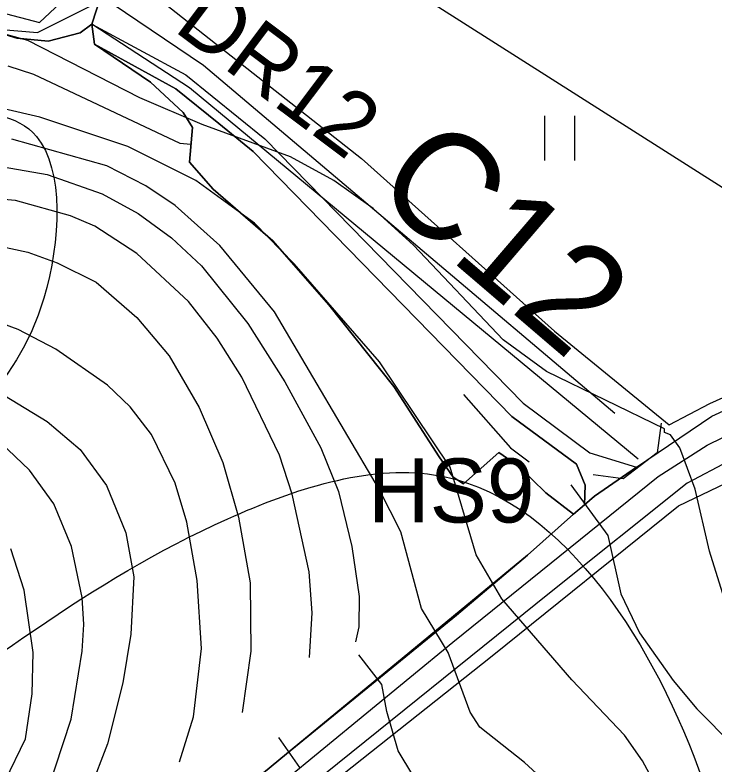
# Model space of a CAD drawing. Extents: x -684583 to -680383, y -1157874 to -1154904.
# Drawn here: x -683367.4 to -683203.8, y -1157172.5 to -1156997 of the extents above; entities that cross this region are included whole.
import ezdxf

# ---------------------------------------------------------------- set-up
doc = ezdxf.new("R2010")
doc.units = 0
for name, color, linetype in [('01_DOPRAVA', 7, 'Continuous'), ('01_PRVKY PRŮZKUMU', 7, 'Continuous'), ('01_VRSTEVNICE', 7, 'Continuous'), ('02_KULTURY STAV', 7, 'Continuous'), ('03_PC_OBJEKTY_NÁVRH', 7, 'Continuous'), ('03_PC_OBJEKTY_STAV', 7, 'Continuous'), ('03_PC_POPIS_STAV', 7, 'Continuous'), ('03_PC_STAV', 7, 'Continuous'), ('04_ZPF_OP_ORGAN', 7, 'Continuous'), ('05_VHO_V_TOK', 7, 'Continuous'), ('06_BIOGEOGRAFIE', 7, 'Continuous'), ('06_ÚSES_BK', 7, 'Continuous')]:
    doc.layers.add(name, color=color, linetype=linetype)

msp = doc.modelspace()

# ---------------------------------------------------------------- linework, layer by layer
at = {"layer": '01_DOPRAVA'}
msp.add_lwpolyline([(-683848.9, -1157421.35), (-683768.73, -1157372.16), (-683751.13, -1157356.37), (-683692.43, -1157298.55), (-683668.13, -1157274.02), (-683656.09, -1157268.45), (-683636.34, -1157266.75), (-683560.15, -1157260.5), (-683520.41, -1157256.3), (-683504.28, -1157253.8), (-683468.06, -1157246.75), (-683377.9, -1157224.15), (-683360.31, -1157216.54), (-683346.34, -1157208.36), (-683325.33, -1157193.59), (-683264.93, -1157143.95), (-683216.9, -1157105.1), (-683205.43, -1157097.83), (-683190.89, -1157090.67), (-683176.02, -1157086.02), (-683159.33, -1157083.06), (-683139, -1157080.79)], dxfattribs=at)
at = {"layer": '01_PRVKY PRŮZKUMU'}
msp.add_lwpolyline([(-683389.86, -1156998.77), (-683362.19, -1157001.09), (-683347.07, -1156993.53), (-683333.41, -1156993.53), (-683286.36, -1157030.61), (-683241.13, -1157071.1), (-683214.31, -1157093.06), (-683204.8, -1157088.06), (-683190.17, -1157081.47)], dxfattribs=at)
at = {"layer": '01_VRSTEVNICE'}
for points in [[(-683173.18, -1157170.81), (-683173.59, -1157160.59), (-683179.58, -1157153.03), (-683188.14, -1157148.33), (-683193.28, -1157144.47), (-683197.7, -1157139.48), (-683201.41, -1157133.63), (-683204.83, -1157122.65), (-683208.25, -1157108.1), (-683211.82, -1157098.4), (-683213.96, -1157095.4), (-683215.39, -1157094.83), (-683215.39, -1157093.98), (-683243.06, -1157080.57), (-683253.19, -1157073.15), (-683274.16, -1157050.9), (-683283.57, -1157042.34), (-683292.84, -1157035.78), (-683302.97, -1157030.22), (-683323.65, -1157022.66), (-683338.2, -1157016.38), (-683364.45, -1157002.97), (-683378.14, -1156999.26)], [(-683326.36, -1157027.36), (-683328.79, -1157027.08), (-683363.02, -1157010.96), (-683369.01, -1157008.96)], [(-683184.43, -1157261.16), (-683198.13, -1157243.61), (-683206.97, -1157226.49), (-683213.25, -1157219.79), (-683215.39, -1157215.37), (-683216.81, -1157209.66), (-683217.1, -1157204.24), (-683215.53, -1157188.27), (-683216.24, -1157182.56), (-683217.81, -1157176.85), (-683220.52, -1157171.72), (-683224.8, -1157165.73), (-683237.07, -1157152.75), (-683253.47, -1157133.78), (-683259.46, -1157123.51), (-683265.6, -1157102.96), (-683282.14, -1157078.29), (-683302.11, -1157055.32), (-683311.39, -1157045.76), (-683325.08, -1157035.78), (-683341.06, -1157027.79), (-683361.6, -1157020.95), (-683377.57, -1157017.24)], [(-683236.93, -1157182.42), (-683248.19, -1157172.15), (-683258.61, -1157163.87), (-683260.89, -1157160.31), (-683266.03, -1157146.33), (-683272.3, -1157136.06), (-683277.15, -1157118.09), (-683282.14, -1157108.24), (-683306.68, -1157066.59), (-683319.52, -1157051.04), (-683329.93, -1157041.63), (-683336.78, -1157037.06), (-683345.91, -1157032.36), (-683368.16, -1157026.08)], [(-683373.86, -1157031.93), (-683359.88, -1157034.35), (-683347.05, -1157038.92), (-683338.63, -1157043.48), (-683330.79, -1157049.19), (-683323.8, -1157055.75), (-683312.95, -1157069.3), (-683304.25, -1157082.99), (-683295.84, -1157098.4), (-683291.7, -1157108.67), (-683288.56, -1157121.51), (-683286.85, -1157133.21), (-683286.99, -1157140.34), (-683287.71, -1157143.9)], [(-683298.47, -1157147.56), (-683297.85, -1157137.06), (-683298.55, -1157127.5), (-683302.54, -1157109.24), (-683305.54, -1157100.11), (-683314.38, -1157081.85), (-683320.09, -1157072.72), (-683326.79, -1157064.17), (-683338.92, -1157052.9), (-683348.76, -1157046.48), (-683354.46, -1157044.05), (-683367.3, -1157040.49), (-683380.14, -1157039.35)], [(-683373.58, -1157050.61), (-683364.45, -1157052.61), (-683357.6, -1157055.04), (-683348.47, -1157059.6), (-683338.92, -1157067.88), (-683331.36, -1157076.86), (-683324.37, -1157088.99), (-683318.8, -1157101.82), (-683315.09, -1157114.66), (-683312.38, -1157130.07), (-683312.24, -1157146.04), (-683314.24, -1157160.45)], [(-683328.9, -1157171.99), (-683325.65, -1157161.45), (-683323.8, -1157145.47), (-683324.79, -1157129.5), (-683327.22, -1157115.8), (-683329.93, -1157106.67), (-683335.49, -1157095.26), (-683340.48, -1157088.84), (-683345.76, -1157083.71), (-683357.89, -1157075.29), (-683366.73, -1157070.73), (-683376.72, -1157067.02)], [(-683373.58, -1157083.99), (-683359.88, -1157092.27), (-683352.18, -1157098.83), (-683346.05, -1157107.24), (-683341.48, -1157118.37), (-683339.63, -1157128.64), (-683340.34, -1157142.05), (-683342.2, -1157153.46), (-683345.76, -1157167.73), (-683349.9, -1157178.57), (-683351.33, -1157186.27), (-683351.33, -1157193.97), (-683349.9, -1157199.68), (-683344.76, -1157208.09)], [(-683262.42, -1157085.93), (-683251.47, -1157098.4), (-683247.05, -1157101.68)], [(-683371.01, -1157210.66), (-683365.45, -1157195.97), (-683354.32, -1157162.02), (-683351.75, -1157146.04), (-683351.33, -1157139.77), (-683351.75, -1157133.49), (-683354.18, -1157121.51), (-683358.32, -1157111.52), (-683364.02, -1157103.68), (-683370.73, -1157097.26)], [(-683237.35, -1157107.1), (-683228.65, -1157118.94), (-683225.66, -1157132.63), (-683221.23, -1157141.76), (-683213.39, -1157152.89), (-683207.83, -1157159.59), (-683190.71, -1157176.85), (-683186.29, -1157183.7), (-683183.01, -1157192.83), (-683180.15, -1157211.09), (-683174.45, -1157232.63)], [(-683369.73, -1157176.43), (-683365.02, -1157166.58), (-683363.45, -1157156.03), (-683363.17, -1157146.33), (-683365.3, -1157131.78), (-683368.44, -1157122.08)], [(-683157.9, -1157343.18), (-683171.45, -1157318.64), (-683184.58, -1157292.97), (-683188.14, -1157287.26), (-683192.85, -1157281.7), (-683198.7, -1157276.13), (-683209.54, -1157268.86), (-683222.23, -1157257.73), (-683229.65, -1157248.75), (-683237.21, -1157237.34), (-683242.35, -1157225.92), (-683246.62, -1157208.81), (-683251.47, -1157197.4), (-683257.04, -1157188.84), (-683260.32, -1157185.56), (-683274.3, -1157175.14), (-683277.72, -1157169.44), (-683280.43, -1157160.17), (-683281.57, -1157153.89), (-683286.99, -1157146.9)], [(-683300.73, -1157173.29), (-683305.67, -1157166.29)]]:
    msp.add_lwpolyline(points, dxfattribs=at)
at = {"layer": '02_KULTURY STAV'}
for points in [[(-683370.86, -1157001.24), (-683367.03, -1157002.46), (-683359.7, -1157003.17), (-683352.15, -1157001.15), (-683349.45, -1156999.14), (-683343.69, -1156981.37), (-683341.48, -1156976.18), (-683337.83, -1156966.11), (-683344.97, -1156965.28), (-683350.67, -1156972.37), (-683355.24, -1156986.1), (-683364.12, -1156994.87), (-683372.87, -1156988.03)], [(-683203.65, -1156985.03), (-683213.41, -1156987.19), (-683225.95, -1156987.87), (-683230.28, -1156988.44), (-683246.03, -1156994.49), (-683251.36, -1156993.14), (-683266.62, -1156985.44), (-683277.18, -1156975.14), (-683289.55, -1156972.59), (-683301.39, -1156969.2), (-683319.75, -1156985.6), (-683331.68, -1156983.88), (-683341.48, -1156976.18), (-683343.69, -1156981.37), (-683349.45, -1156999.14), (-683327.49, -1157011.01), (-683308.96, -1157026.01), (-683248.52, -1157087.99), (-683232.88, -1157099.6), (-683221.99, -1157102.98), (-683204.36, -1157091.01), (-683192.73, -1157085.68)], [(-683370.86, -1157001.24), (-683367.03, -1157002.46), (-683359.7, -1157003.17), (-683352.15, -1157001.15), (-683349.45, -1156999.14), (-683348.81, -1157003.81), (-683335.7, -1157012.73), (-683328.09, -1157019.82), (-683325.91, -1157023.37), (-683326.6, -1157031.51), (-683321.09, -1157037.79), (-683307.07, -1157049.92), (-683293.99, -1157064.88), (-683278.77, -1157084.06), (-683268.17, -1157100.5), (-683264.9, -1157105.28), (-683262.45, -1157106.87), (-683254.22, -1157099.55), (-683249.56, -1157102.68), (-683243.17, -1157108.95), (-683236.68, -1157113.93), (-683247.5, -1157123.53), (-683303.88, -1157170.13), (-683333.9, -1157194.91)], [(-683243.5, -1157020.6), (-683243.5, -1157031.1)], [(-683236.5, -1157020.6), (-683236.5, -1157031.1)], [(-683333.9, -1157194.91), (-683303.88, -1157170.13), (-683264.09, -1157137.63), (-683247.5, -1157123.53), (-683236.68, -1157113.93), (-683234.11, -1157111.74), (-683231.81, -1157109.78), (-683221.99, -1157102.98), (-683204.36, -1157091.01), (-683192.73, -1157085.68), (-683177.22, -1157080.76), (-683161.41, -1157076.94), (-683151.59, -1157072.03), (-683141.73, -1157064.85), (-683156.58, -1157097.8), (-683159.7, -1157092.45), (-683164.59, -1157091.26), (-683175.94, -1157092.6), (-683190.37, -1157096.97), (-683200.33, -1157101.53), (-683210.06, -1157106.68), (-683242.35, -1157132.43), (-683297.96, -1157177.33)]]:
    msp.add_lwpolyline(points, dxfattribs=at)
for points in [[(-683349.45, -1156999.14), (-683327.49, -1157011.01), (-683308.96, -1157026.01), (-683248.52, -1157087.99), (-683232.88, -1157099.6), (-683221.99, -1157102.98), (-683231.81, -1157109.78), (-683234.11, -1157111.74), (-683233.99, -1157107.14), (-683236, -1157102.26), (-683251.17, -1157091.07), (-683311.69, -1157028.98), (-683319.75, -1157022.45), (-683329.81, -1157014.3), (-683348.81, -1157003.81)], [(-683348.81, -1157003.81), (-683329.81, -1157014.3), (-683319.75, -1157022.45), (-683311.69, -1157028.98), (-683251.17, -1157091.07), (-683236, -1157102.26), (-683233.99, -1157107.14), (-683234.11, -1157111.74), (-683236.68, -1157113.93), (-683243.17, -1157108.95), (-683249.56, -1157102.68), (-683254.22, -1157099.55), (-683262.45, -1157106.87), (-683264.9, -1157105.28), (-683268.17, -1157100.5), (-683278.77, -1157084.06), (-683293.99, -1157064.88), (-683307.07, -1157049.92), (-683321.09, -1157037.79), (-683326.6, -1157031.51), (-683325.91, -1157023.37), (-683328.09, -1157019.82), (-683335.7, -1157012.73)]]:
    msp.add_lwpolyline(points, close=True, dxfattribs=at)
at = {"layer": '03_PC_OBJEKTY_NÁVRH'}
msp.add_lwpolyline([(-683226.99, -1157090.37), (-683323.32, -1157008.82), (-683344.73, -1156994.4)], dxfattribs=at)
at = {"layer": '03_PC_OBJEKTY_STAV'}
msp.add_lwpolyline([(-683216.16, -1157092.62), (-683217.11, -1157099.62), (-683225.07, -1157105.68), (-683232.08, -1157104.73)], dxfattribs=at)
at = {"layer": '03_PC_STAV'}
msp.add_lwpolyline([(-683221.6, -1157101.06), (-683326.6, -1157014.04), (-683349.45, -1156999.14)], dxfattribs=at)
at = {"layer": '04_ZPF_OP_ORGAN'}
msp.add_lwpolyline([(-683343.12, -1157216.48), (-683255.77, -1157147.12), (-683212.14, -1157111.99), (-683188, -1157100.46), (-683171.81, -1157095.24), (-683160.28, -1157100.46), (-683176.2, -1157149.05), (-683182.23, -1157222.89), (-683169.61, -1157275.32), (-683083.46, -1157449.64), (-683050.81, -1157531.17), (-683043.68, -1157605.57), (-683055.75, -1157649.76), (-683061.24, -1157640.16), (-683077.15, -1157575.37), (-683110.35, -1157581.68), (-683135.87, -1157597.03), (-683152.6, -1157616.55), (-683323.54, -1157289.05), (-683339.45, -1157238.26)], close=True, dxfattribs=at)
at = {"layer": '05_VHO_V_TOK'}
msp.add_lwpolyline([(-683378.73, -1156994.28), (-683361.67, -1156998.74), (-683352.07, -1156989.61), (-683342.95, -1156971), (-683334.18, -1156973.73), (-683324.11, -1156981.32), (-683316.17, -1156975.87), (-683302.3, -1156964.48), (-683279.9, -1156970.88), (-683268.64, -1156977.76), (-683256.2, -1156986.41), (-683238.07, -1156986.41), (-683206.55, -1156982.5), (-683191.86, -1156974.2), (-683180.36, -1156978.71), (-683174.44, -1156992.7), (-683172.9, -1157010.12), (-683165.9, -1157018.9), (-683149.43, -1157022.45), (-683104.87, -1157050.79), (-683100.25, -1157059.8), (-683098, -1157072.96), (-683095.63, -1157123.11), (-683121.58, -1157197.8)], dxfattribs=at)
at = {"layer": '06_BIOGEOGRAFIE'}
for points in [[(-683605.53, -1156693.94), (-683552.15, -1156773.17), (-683505.66, -1156862.74), (-683385.12, -1156876.52), (-683240.48, -1156867.91), (-682983.91, -1156935.09), (-682923.69, -1156998.38), (-682921.97, -1157094.84), (-682923.69, -1157198.19), (-682892.7, -1157272.26), (-682746.33, -1157329.1), (-682572.41, -1157337.72), (-682417.44, -1157289.49), (-682386.73, -1157266.62)], [(-683662.04, -1156787.77), (-683658.6, -1156877.34), (-683631.05, -1156927.29), (-683541.5, -1156975.52), (-683489.85, -1157028.92), (-683414.08, -1157027.2), (-683362.42, -1157025.48), (-683360.7, -1157063.37), (-683464.02, -1157132.27), (-683493.29, -1157163.28), (-683474.35, -1157189.11), (-683407.19, -1157171.89), (-683317.65, -1157115.05), (-683269.44, -1157104.71), (-683207.44, -1157173.61), (-683186.78, -1157259.74), (-683105.85, -1157416.48), (-683069.69, -1157530.17), (-683073.13, -1157580.12), (-683097.24, -1157628.35), (-683264.27, -1157657.63), (-683431.3, -1157647.3), (-683531.17, -1157605.96), (-683636.21, -1157542.23), (-683651.71, -1157521.56), (-683682.7, -1157519.83), (-683708.53, -1157528.45), (-683818.74, -1157547.39), (-683870.4, -1157518.11), (-683980.6, -1157521.56), (-684052.92, -1157490.55), (-684171.74, -1157400.98), (-684213.07, -1157375.14), (-684250.95, -1157388.92), (-684249.23, -1157437.15), (-684237.17, -1157466.44), (-684170.02, -1157518.11), (-684097.7, -1157562.9), (-684011.6, -1157605.96), (-683953.05, -1157602.51), (-683891.06, -1157626.63), (-683835.96, -1157619.74), (-683789.47, -1157599.07), (-683713.7, -1157578.4), (-683625.88, -1157592.18), (-683551.84, -1157667.97), (-683445.07, -1157736.87), (-683346.92, -1157771.32), (-683179.89, -1157767.87), (-683081.74, -1157773.04), (-683016.71, -1157810.65), (-682999.16, -1157844)]]:
    msp.add_spline(points, degree=3, dxfattribs=at)
at = {"layer": '06_ÚSES_BK'}
msp.add_lwpolyline([(-683158.62, -1157178.84), (-683156.25, -1157161.12), (-683151.27, -1157139.55), (-683145.65, -1157125.76), (-683142.92, -1157117.14), (-683133.51, -1157096.13), (-683130.44, -1157090.32), (-683127.87, -1157085.44), (-683146.23, -1157074.82), (-683146.88, -1157076.28), (-683149.7, -1157070.65), (-683281.53, -1156986.77), (-683319.75, -1156985.6), (-683331.68, -1156983.88), (-683343.69, -1156981.37), (-683347.61, -1156993.23), (-683349.45, -1156999.14), (-683352.15, -1157001.15), (-683359.7, -1157003.17), (-683367.03, -1157002.46), (-683370.86, -1157001.24)], dxfattribs=at)

# ---------------------------------------------------------------- texts
at = {"layer": '03_PC_OBJEKTY_NÁVRH'}
msp.add_text('DR12', height=15, rotation=323.1279, dxfattribs=at).set_placement((-683330.6, -1157000.5))
at = {"layer": '03_PC_OBJEKTY_STAV'}
msp.add_text('HS9', height=15, dxfattribs=at).set_placement((-683284.85, -1157115.91))
at = {"layer": '03_PC_POPIS_STAV'}
msp.add_text('C12', height=25, rotation=319.4103, dxfattribs=at).set_placement((-683284.28, -1157038.35))

doc.saveas('drawing.dxf')
